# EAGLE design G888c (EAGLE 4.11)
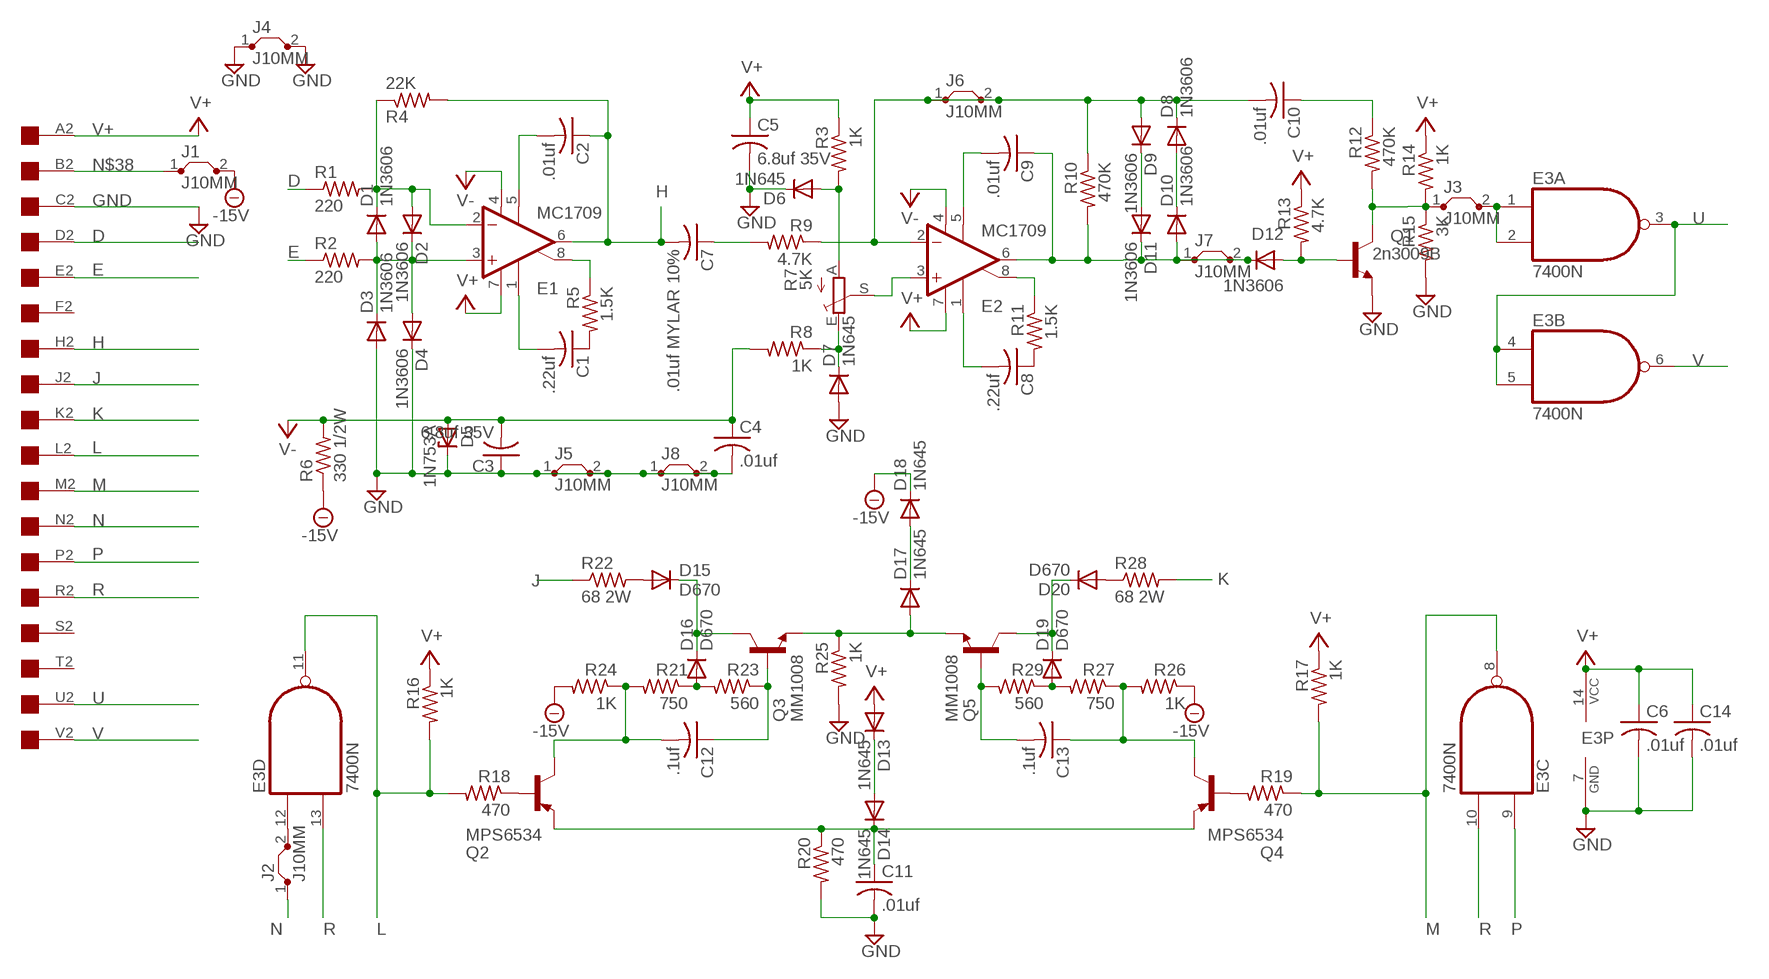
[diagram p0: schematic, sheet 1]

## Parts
C1  .22uf  C-US050-025X075  [C050-025X075]
C2  .01uf  C-US050-025X075  [C050-025X075]
C3  6.8uf 35V  C-US102-043X133  [C102-043X133]
C4  .01uf  C-US050-025X075  [C050-025X075]
C5  6.8uf 35V  C-US102-043X133  [C102-043X133]
C6  .01uf  C-US050-025X075  [C050-025X075]
C7  .01uf MYLAR 10%  C-US150-054X183  [C150-054X183]
C8  .22uf  C-US050-025X075  [C050-025X075]
C9  .01uf  C-US050-025X075  [C050-025X075]
C10  .01uf  C-US050-025X075  [C050-025X075]
C11  .01uf  C-US050-025X075  [C050-025X075]
C12  .1uf  C-US050-025X075  [C050-025X075]
C13  .1uf  C-US050-025X075  [C050-025X075]
C14  .01uf  C-US050-025X075  [C050-025X075]
D1  1N3606  1N4004  [DO41-10]
D2  1N3606  1N4004  [DO41-10]
D3  1N3606  1N4004  [DO41-10]
D4  1N3606  1N4004  [DO41-10]
D5  1N753A  ZENER-DIODEDO35Z10  [DO35Z10]
D6  1N645  1N4004  [DO41-10]
D7  1N645  1N4004  [DO41-10]
D8  1N3606  1N4004  [DO41-10]
D9  1N3606  1N4004  [DO41-10]
D10  1N3606  1N4004  [DO41-10]
D11  1N3606  1N4004  [DO41-10]
D12  1N3606  1N4004  [DO41-10]
D13  1N645  1N4004  [DO41-10]
D14  1N645  1N4004  [DO41-10]
D15  D670  1N4004  [DO41-10]
D16  D670  1N4004  [DO41-10]
D17  1N645  1N4004  [DO41-10]
D18  1N645  1N4004  [DO41-10]
D19  D670  1N4004  [DO41-10]
D20  D670  1N4004  [DO41-10]
E1  MC1709  LM3080N  [DIL08]
E2  MC1709  LM3080N  [DIL08]
E3  7400N  [DIL14]
J1  J10MM  [10]
J2  J10MM  [10]
J3  J10MM  [10]
J4  J10MM  [10]
J5  J10MM  [10]
J6  J10MM  [10]
J7  J10MM  [10]
J8  J10MM  [10]
Q1  2n3009B  2N1711  [TO39]
Q2  MPS6534  2N5415  [TO39]
Q3  MM1008  2N1711  [TO39]
Q4  MPS6534  2N5415  [TO39]
Q5  MM1008  2N1711  [TO39]
R1  220  R-US_0207/10  [0207/10]
R2  220  R-US_0207/10  [0207/10]
R3  1K  R-US_0207/10  [0207/10]
R4  22K  R-US_0207/10  [0207/10]
R5  1.5K  R-US_0207/10  [0207/10]
R6  330 1/2W  R-US_0411/15  [0411/15]
R7  5K  TRIM_EU-PTSPIN  [PT-SPIN]
R8  1K  R-US_0207/10  [0207/10]
R9  4.7K  R-US_0207/10  [0207/10]
R10  470K  R-US_0207/10  [0207/10]
R11  1.5K  R-US_0207/10  [0207/10]
R12  470K  R-US_0207/10  [0207/10]
R13  4.7K  R-US_0207/10  [0207/10]
R14  1K  R-US_0207/10  [0207/10]
R15  3K  R-US_0207/10  [0207/10]
R16  1K  R-US_0207/10  [0207/10]
R17  1K  R-US_0207/10  [0207/10]
R18  470  R-US_0207/10  [0207/10]
R19  470  R-US_0207/10  [0207/10]
R20  470  R-US_0207/10  [0207/10]
R21  750  R-US_0207/10  [0207/10]
R22  68 2W  R-US_0817/22  [P0817/22]
R23  560  R-US_0207/10  [0207/10]
R24  1K  R-US_0207/10  [0207/10]
R25  1K  R-US_0207/10  [0207/10]
R26  1K  R-US_0207/10  [0207/10]
R27  750  R-US_0207/10  [0207/10]
R28  68 2W  R-US_0817/22  [P0817/22]
R29  560  R-US_0207/10  [0207/10]
U$5  ONE-SIDED  [ONE-SIDED]

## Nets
-15V: D18.C J1.2 R6.1 R24.2 R26.1
D: R1.1 U$5.D2
E: R2.1 U$5.E2
GND: C3.1 C4.2 C5.2 C6.2 C11.2 C14.2 D3.A D4.C D5.C D6.C D7.A E3.7(P:GND) J4.1 J4.2 J5.1 J5.2 J8.1 J8.2 Q1.1(E) R15.2 R20.2 R25.2 U$5.C2
H: C2.1 C7.2 E1.6(OUT) R4.2 U$5.H2
J: R22.1 U$5.J2
K: R28.2 U$5.K2
L: E3.11(D:O) R16.2 R18.2 U$5.L2
M: E3.8(C:O) R17.2 R19.1 U$5.M2
N: J2.1 U$5.N2
N$1: C1.1 R5.2
N$2: C8.1 R11.2
N$3: D1.C D2.A E1.2(-IN) R1.2 R4.1
N$4: D1.A D2.C D3.C D4.A E1.3(+IN) R2.2
N$5: C8.2 E2.1(ON1)
N$6: C1.2 E1.1(ON1)
N$7: E1.8(ON2) R5.1
N$8: C2.2 E1.5(OPT)
N$9: D6.A R3.2 R7.A
N$10: C10.2 D8.C D9.A E2.2(-IN) J6.1 J6.2 R9.1 R10.1
N$11: E2.3(+IN) R7.S
N$12: D7.C R7.E R8.1
N$13: E2.8(ON2) R11.1
N$14: C9.2 E2.5(OPT)
N$15: C9.1 D10.A D11.C D12.C E2.6(OUT) J7.1 J7.2 R10.2
N$16: C7.1 R9.2
N$17: D9.C D11.A
N$18: D8.A D10.C
N$19: C10.1 R12.1
N$20: D12.A Q1.2(B) R13.2
N$21: J3.1 Q1.3(C) R12.2 R14.2 R15.1
N$22: D17.A Q3.1(E) Q5.1(E) R25.1
N$23: C11.1 D14.C Q2.1(E) Q4.1(E) R20.1
N$24: D13.C D14.A
N$25: Q2.2(B) R18.1
N$26: Q4.2(B) R19.2
N$27: D15.A R22.2
N$28: D16.A R21.1 R23.2
N$29: C12.2 Q2.3(C) R21.2 R24.1
N$30: C12.1 Q3.2(B) R23.1
N$31: D19.A R27.2 R29.1
N$32: C13.1 Q4.3(C) R26.2 R27.1
N$33: C13.2 Q5.2(B) R29.2
N$34: D20.A R28.1
N$35: D15.C D16.C Q3.3(C)
N$36: D19.C D20.C Q5.3(C)
N$37: D17.C D18.A
N$38: J1.1 U$5.B2
N$39: E3.12(D:I0) J2.2
N$40: E3.1(A:I0) E3.2(A:I1) J3.2
P: E3.9(C:I0) U$5.P2
R: E3.10(C:I1) E3.13(D:I1) U$5.R2
U: E3.3(A:O) E3.4(B:I0) E3.5(B:I1) U$5.U2
V: E3.6(B:O) U$5.V2
V+: C5.1 C6.1 C14.1 D13.A E1.7(V+) E2.7(V+) E3.14(P:VCC) R3.1 R13.1 R14.1 R16.1 R17.1 U$5.A2
V-: C3.2 C4.1 D5.A E1.4(V-) E2.4(V-) R6.2 R8.2
Unconnected: U$5.F2 U$5.S2 U$5.T2

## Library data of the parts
C1-C14 = rcl:C-US: CAPACITOR, American symbol
D1-D4 D6-D20 = diode:1N4004: DIODE
D5 = diode:ZENER-DIODE: Z-Diode
E1 E2 = linear:*3080: OP AMP
E3 = 74xx-us:74*00: Quad 2-input NAND gate
J1-J8 = jumper:J: Bridge
Q1 Q3 Q5 = transistor-npn:2N1711: NPN Transistor
Q2 Q4 = transistor-pnp:2N5415*: PNP Transistror
R1-R6 R8-R29 = rcl:R-US_: RESISTOR, American symbol
R7 = pot:TRIM_EU-: POTENTIOMETER
U$5 = con-dec:ONE-SIDED: One-sided DEC Flip-Chip single card fingers

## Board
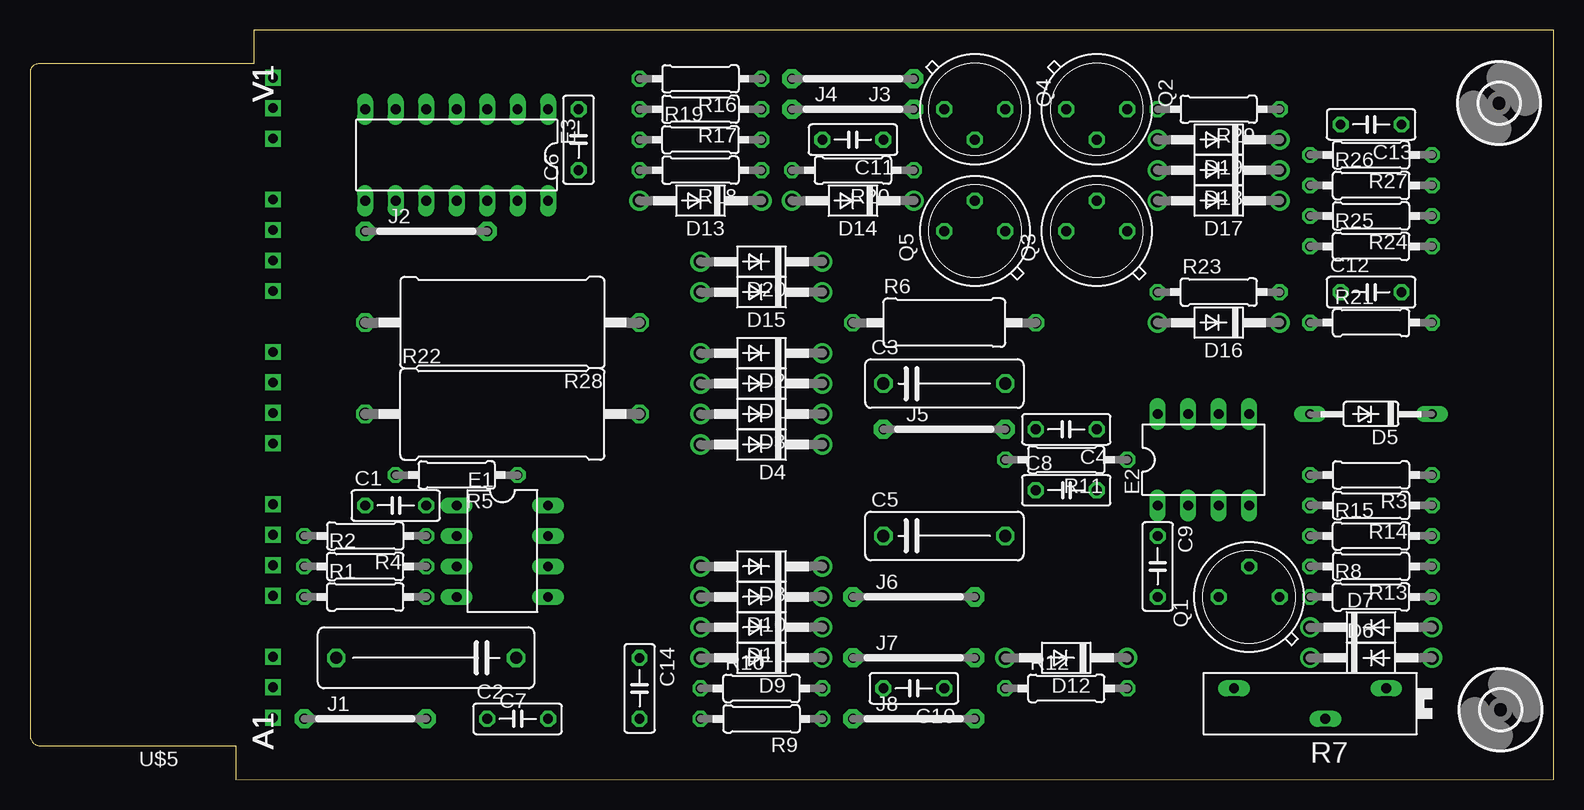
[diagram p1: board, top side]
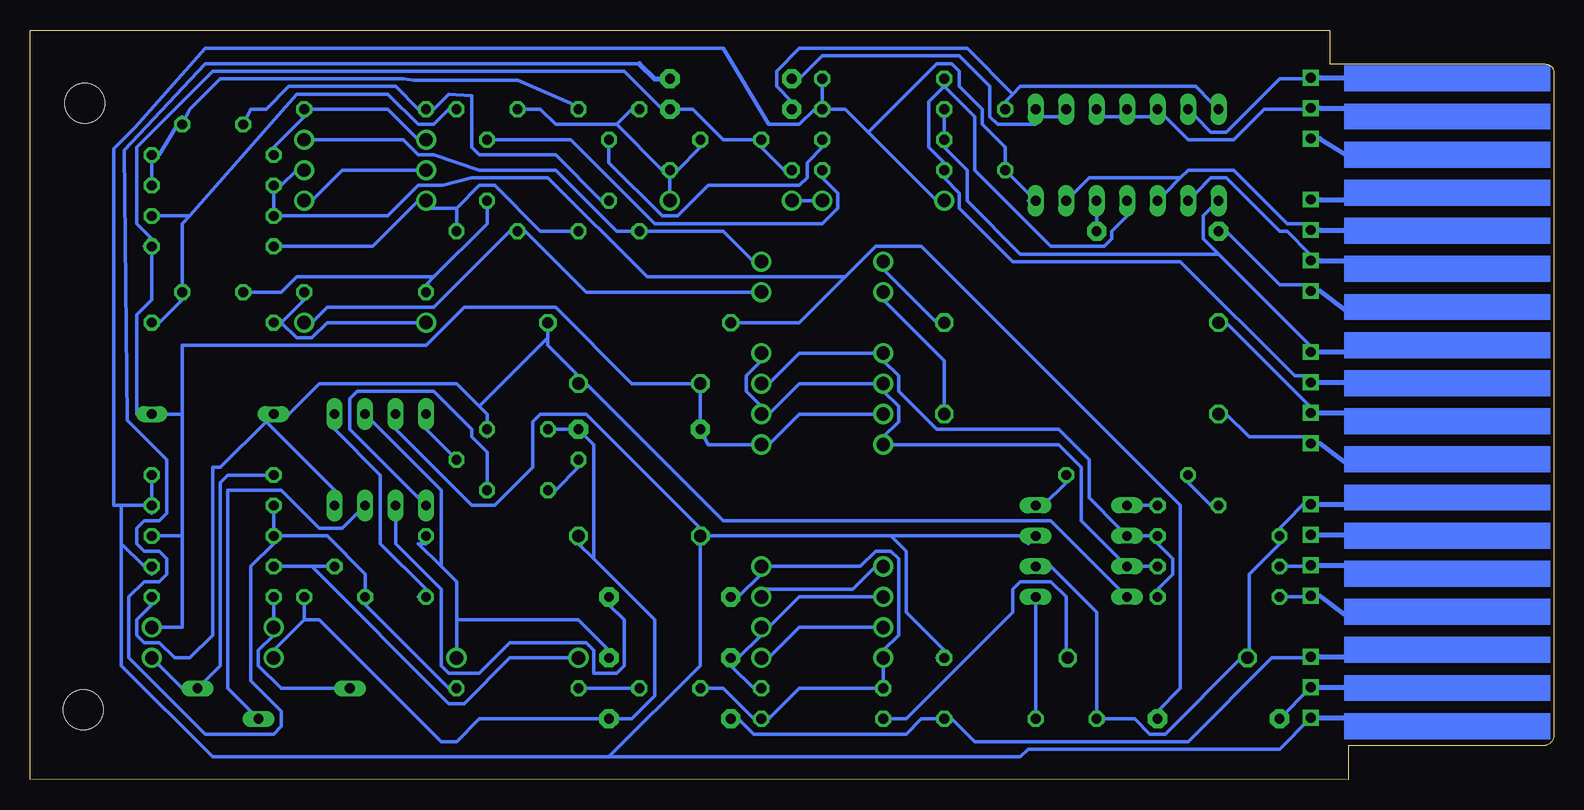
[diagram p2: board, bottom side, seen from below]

Size 126.98 x 62.48 mm. Coordinates in mm from the lower left corner, seen from the top.
Outline: 17.14,2.83 17.14,0 126.98,0.04 126.98,62.45 18.66,62.48 18.66,59.65 0.69,59.65 arc90 0,58.96 0,3.72 arc90 0.89,2.83 17.14,2.83
Copper layers (1*16): Top 0.035mm / dielectric 1.5mm / Bottom 0.035mm
Design rules "10mils": minimum track width 12mil, minimum drill 28mil, track to track 10mil, track to pad 10mil, pad to pad 10mil, via to via 10mil, smd to smd 10mil, copper to edge 40mil, drill to drill 10mil, minimum pad ring 10mil, minimum via ring 8mil, stop-mask expansion 0mil, vias tented up to drill 0mil, thermal gap 10mil

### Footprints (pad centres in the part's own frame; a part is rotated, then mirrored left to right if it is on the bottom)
C050-025X075 = drill 0.813 octagon: 1 -2.54,0; 2 2.54,0
C102-043X133 = drill 1.016 octagon: 1 -5.08,0; 2 5.08,0
C150-054X183 = drill 1.016 octagon: 1 -7.493,0; 2 7.493,0
DO41-10 = drill 1.118 round: A 5.08,0; C -5.08,0
DO35Z10 = drill 0.813 long: A 5.08,0; C -5.08,0
DIL08 = drill 0.813 long: 1 -3.81,-3.81; 2 -1.27,-3.81; 3 1.27,-3.81; 4 3.81,-3.81; 5 3.81,3.81; 6 1.27,3.81; 7 -1.27,3.81; 8 -3.81,3.81
DIL14 = drill 0.813 long: 1 -7.62,-3.81; 2 -5.08,-3.81; 3 -2.54,-3.81; 4 0,-3.81; 5 2.54,-3.81; 6 5.08,-3.81; 7 7.62,-3.81; 8 7.62,3.81; 9 5.08,3.81; 10 2.54,3.81; 11 0,3.81; 12 -2.54,3.81; 13 -5.08,3.81; 14 -7.62,3.81
10 = drill 0.813 pad 1.6 octagon: 1 -5.08,0; 2 5.08,0
TO39 = drill 0.813 octagon: 1 0,-2.54; 2 2.54,0; 3 0,2.54
0207/10 = drill 0.813 octagon: 1 -5.08,0; 2 5.08,0
0411/15 = drill 0.914 octagon: 1 -7.62,0; 2 7.62,0
PT-SPIN = drill 0.813 long: A -6.35,-1.27; E 6.35,-1.27; S -1.27,1.27
P0817/22 = drill 1.016 octagon: 1 -11.43,0; 2 11.43,0
3,3 = hole 3.3: 0,0
ONE-SIDED = drill 0.813 square: A2 20.256,5.175; B2 20.256,7.715; C2 20.256,10.255; D2 20.256,15.335; E2 20.256,17.875; F2 20.256,20.415; H2 20.256,22.955; J2 20.256,28.035; K2 20.256,30.575; L2 20.256,33.115; M2 20.256,35.655; N2 20.256,40.735; P2 20.256,43.275; R2 20.256,45.815; S2 20.256,48.355; T2 20.256,53.435; U2 20.256,55.975; V2 20.256,58.515

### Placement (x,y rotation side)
C1  30.48,22.86 0 top
C2  40.63,5.08 0 top
C3  76.2,33.02 0 top
C4  86.36,29.21 180 top
C5  76.2,20.32 0 top
C6  45.71,53.34 90 top
C7  33.02,10.16 180 top
C8  86.36,24.13 0 top
C9  93.98,17.78 270 top
C10  73.66,7.62 180 top
C11  68.58,53.34 180 top
C12  111.76,40.64 0 top
C13  111.76,54.61 180 top
C14  50.79,7.62 270 top
D1  60.95,33.02 180 top
D2  60.95,35.56 180 top
D3  60.95,30.48 180 top
D4  60.95,27.94 180 top
D5  111.76,30.48 180 top
D6  111.76,10.16 0 top
D7  111.76,12.7 0 top
D8  60.95,17.78 180 top
D9  60.95,10.16 180 top
D10  60.95,15.24 180 top
D11  60.95,12.7 180 top
D12  86.36,10.16 180 top
D13  55.88,48.26 180 top
D14  68.58,48.26 180 top
D15  60.95,40.64 180 top
D16  99.06,38.1 180 top
D17  99.06,48.26 180 top
D18  99.06,50.8 180 top
D19  99.06,53.34 180 top
D20  60.95,43.18 180 top
E1  39.36,19.05 270 top
E2  97.79,26.67 0 top
E3  35.55,52.07 180 top
J1  27.94,5.08 0 top
J2  33.02,45.72 0 top
J3  68.58,58.42 180 top
J4  68.58,55.88 0 top
J5  76.2,29.21 0 top
J6  73.66,15.24 0 top
J7  73.66,10.16 0 top
J8  73.66,5.08 0 top
Q1  101.59,15.24 90 top
Q2  88.9,55.88 270 top
Q3  88.9,45.72 90 top
Q4  78.73,55.88 270 top
Q5  78.73,45.72 90 top
R1  27.94,15.24 0 top
R2  27.94,17.78 0 top
R3  111.76,25.4 180 top
R4  27.94,20.32 180 top
R5  35.55,25.4 180 top
R6  76.2,38.1 0 top
R7  106.68,6.35 180 top
R8  111.76,15.24 0 top
R9  60.95,5.08 180 top
R10  60.95,7.62 0 top
R11  86.36,26.67 180 top
R12  86.36,7.62 0 top
R13  111.76,17.78 180 top
R14  111.76,22.86 180 top
R15  111.76,20.32 0 top
R16  55.88,58.42 180 top
R17  55.88,55.88 180 top
R18  55.88,50.8 180 top
R19  55.88,53.34 0 top
R20  68.58,50.8 180 top
R21  111.76,38.1 0 top
R22  39.36,30.48 0 top
R23  99.06,40.64 0 top
R24  111.76,46.99 180 top
R25  111.76,44.45 0 top
R26  111.76,49.53 0 top
R27  111.76,52.07 180 top
R28  39.36,38.1 180 top
R29  99.06,55.88 180 top
U$2  [3,3]  122.42,56.39 0 top
U$3  [3,3]  122.55,5.84 0 top
U$5  -0.01,0 0 top

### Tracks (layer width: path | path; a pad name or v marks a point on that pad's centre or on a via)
-15V
  Bottom 0.305: 59.05,41.91 56.51,44.45 52.7,44.45 31.11,22.86 31.11,7.62 33.02,5.71 J1.2 | 59.05,41.91 62.86,38.1 67.94,38.1 R6.1 | D18.C 104.77,50.8 106.04,49.53 R26.1 106.68,48.9 106.68,47.62 R24.2 106.04,46.99 104.77,46.99 97.15,46.99 94.61,49.53 92.58,49.53 90.17,50.16 83.81,50.16 75.56,41.91 59.05,41.91
D
  Bottom 0.305: U$5.D2 20.32,15.24 22.22,15.24 R1.1
E
  Bottom 0.305: U$5.E2 20.32,17.78 22.22,17.78 R2.1
GND
  Top 0.305: J4.1 64.13,55.88 67.94,55.88 73.02,55.88 J4.2 | J8.1 69.21,5.08
  Top 0.406: 69.21,5.08 J8.2 | J5.2 J5.1
  Bottom 0.305: 81.28,20.95 C5.2 81.28,19.68 80.01,18.41 | D3.A 56.51,30.48 62.86,30.48 65.4,27.94 D4.C 66.67,27.94 70.48,27.94 J5.1 71.12,28.57 71.12,32.38 C3.1 71.75,33.02 76.83,33.02 83.18,39.37 90.8,39.37 93.98,36.2 114.3,36.2 114.3,30.48 | J8.2 78.1,5.08 | U$5.C2 20.32,10.16 23.49,10.16 30.48,3.17 48.25,3.17 50.16,5.08 C14.2 51.43,5.08 52.7,5.08 53.97,3.81 66.67,3.81 67.94,5.08 J8.1 | 78.1,5.08 76.83,5.08 74.93,6.99 74.93,13.34 80.01,18.41 | J8.2 78.1,5.08 | J8.2 79.37,5.08 89.53,5.08 91.44,3.17 92.7,3.17 102.87,13.34 104.14,13.34 | 114.3,20.32 114.3,16.51 114.3,12.7 116.2,12.7 D7.A | 45.08,57.15 45.71,56.52 C6.2 | 45.08,57.15 44.45,57.78 29.84,57.78 28.57,56.52 E3.7 | 45.08,57.15 48.89,60.96 62.86,60.96 64.77,59.05 64.77,57.78 63.49,56.52 J4.1 | 104.14,13.34 104.14,14.61 Q1.1 | 104.14,13.34 106.68,10.79 D6.C | 114.3,20.32 116.2,20.32 R15.2 | 80.01,18.41 80.01,26.04 80.01,27.94 J5.2 81.91,29.21 83.18,29.21 C4.2 | R20.2 64.13,50.8 66.04,52.7 C11.2 66.67,53.34 69.21,53.34 71.75,55.88 73.02,55.88 J4.2 | 74.29,55.88 J4.2 | 114.3,30.48 114.3,20.32 | 114.3,30.48 115.56,30.48 D5.C 118.11,30.48 118.11,38.73 116.84,40.01 116.84,43.81 R25.2 | R25.2 117.47,44.45 | 74.29,55.88 77.47,59.05 111.76,59.05 118.11,52.7 118.11,46.35 116.84,45.09 R25.2 | 74.29,55.88 J4.2
H
  Bottom 0.305: U$5.H2 20.32,23.5 22.86,20.95 R4.2 22.86,19.68 25.39,17.14 25.39,10.79 C7.2 26.03,10.16 32.38,3.81 33.65,3.81 34.92,5.08 37.46,5.08 C2.1 38.09,5.71 38.09,13.97 41.9,17.78 E1.6
J
  Bottom 0.305: U$5.J2 20.32,28.57 25.39,28.57 27.3,30.48 R22.1
K
  Bottom 0.305: U$5.K2 20.32,31.11 27.3,38.1 R28.2
L
  Bottom 0.305: U$5.L2 20.32,33.66 21.59,33.66 31.11,43.18 45.08,43.18 49.52,47.62 49.52,48.9 50.79,50.16 R18.2 50.79,51.44 52.06,52.7 52.06,56.52 50.79,57.78 | 50.79,57.78 R16.2 50.79,57.78 | 50.79,57.78 48.25,55.24 48.25,50.8 41.9,44.45 37.46,44.45 36.82,45.09 36.82,45.72 35.55,46.99 E3.11
  Bottom 0.406: R16.2 50.79,57.91
M
  Bottom 0.305: 27.94,43.81 20.32,36.2 U$5.M2 | 27.94,43.81 28.57,44.45 29.21,45.09 29.21,46.99 28.57,47.62 E3.8 | R19.1 50.79,53.98 50.79,55.24 R17.2 | 50.79,52.7 R19.1 | 50.79,52.7 48.89,50.8 48.89,48.26 44.45,43.81 27.94,43.81 | 50.79,52.7 R19.1
N
  Bottom 0.305: U$5.N2 20.32,41.27 22.86,41.27 27.3,45.72 J2.1
N$1
  Bottom 0.305: C1.1 28.57,22.86 30.48,24.77 R5.2
N$2
  Bottom 0.305: C8.1 83.18,24.13 81.28,26.04 R11.2
N$3
  Bottom 0.305: R1.2 33.02,15.88 31.75,17.14 31.75,18.41 33.02,19.68 R4.1 33.65,20.32 34.28,20.32 E1.2 36.19,20.95 38.73,23.5 38.73,26.67 41.27,29.21 51.43,29.21 54.6,32.38 54.6,33.66 55.88,34.92 D2.A 56.51,35.56 62.86,35.56 65.4,33.02 D1.C
N$4
  Bottom 0.305: R2.2 33.65,17.78 34.28,17.78 E1.3 36.19,18.41 39.36,21.59 39.36,26.04 41.27,27.94 55.24,27.94 D4.A 55.88,28.57 54.6,29.84 54.6,31.11 55.88,32.38 D1.A 56.51,33.02 62.86,33.02 65.4,30.48 D3.C 66.04,31.11 67.31,32.38 67.31,33.66 66.04,34.92 D2.C
N$5
  Bottom 0.305: E2.1 94.61,23.5 100.33,29.21 100.33,31.75 99.69,32.38 93.34,32.38 90.17,29.21 90.17,28.57 88.9,27.3 88.9,24.77 C8.2
N$6
  Bottom 0.305: C1.2 33.65,22.86 34.28,22.86 E1.1
N$7
  Bottom 0.305: R5.1 40.63,24.77 42.54,22.86 E1.8
N$8
  Bottom 0.305: C2.2 43.17,5.71 43.17,14.61 E1.5
N$9
  Bottom 0.305: D6.A 114.3,7.62 R7.A 112.39,8.26 111.12,9.53 111.12,24.77 110.48,25.4 107.31,25.4 R3.2
N$10
  Top 0.406: J6.1 J6.2
  Bottom 0.305: C10.2 70.48,7.62 69.21,7.62 66.67,5.08 R9.1 65.4,5.08 62.86,7.62 56.51,7.62 R10.1 55.88,8.26 55.88,9.53 D9.A 55.88,10.79 54.6,12.06 54.6,18.41 55.24,19.05 56.51,19.05 57.78,17.78 65.4,17.78 D8.C 66.04,17.14 67.94,15.24 J6.1 68.58,15.88 | 79.37,15.24 J6.2 78.73,14.61 77.47,13.34 77.47,9.53 78.1,8.89 80.01,8.89 80.01,10.79 80.64,11.43 86.99,11.43 89.53,8.89 92.07,8.89 92.7,9.53 92.7,15.88 96.52,19.68 96.52,21.59 E2.2
N$11
  Bottom 0.305: 108.58,5.71 R7.S 108.58,5.71 | 108.58,5.71 110.48,7.62 110.48,24.13 106.04,24.13 102.87,20.95 100.96,20.95 99.69,22.23 E2.3
N$12
  Bottom 0.305: R7.E 101.59,7.62 106.04,7.62 107.95,9.53 107.95,10.79 106.68,12.06 D7.C 106.68,13.34 106.68,14.61 R8.1
N$13
  Bottom 0.305: R11.1 93.98,29.21 E2.8
N$14
  Bottom 0.305: 94.61,15.24 C9.2 93.98,15.88 97.79,19.68 97.79,25.4 101.59,29.21 E2.5
N$15
  Top 0.305: J7.1 69.21,10.16
  Top 0.406: 69.21,10.16 J7.2
  Bottom 0.305: 91.44,13.34 91.44,16.51 92.7,17.78 | 91.44,13.34 91.44,10.79 D12.C | 93.98,19.68 C9.1 93.98,19.68 | D10.A 56.51,15.24 62.86,15.24 65.4,12.7 D11.C 66.04,12.06 67.94,10.16 J7.1 68.58,9.53 66.67,7.62 R10.2 | 91.44,13.34 81.28,13.34 78.73,10.79 J7.2 | 92.7,17.78 94.61,19.68 93.98,19.68 | 92.7,17.78 92.7,24.13 98.42,29.84 E2.6
N$16
  Bottom 0.305: R9.2 55.24,5.08 53.97,5.08 45.08,13.97 45.08,15.88 44.45,16.51 41.9,16.51 40.63,15.24 40.63,10.79 C7.1
N$17
  Bottom 0.305: D11.A 56.51,12.7 62.86,12.7 65.4,10.16 D9.C
N$18
  Bottom 0.305: D8.A 56.51,17.78 58.41,15.88 66.04,15.88 D10.C
N$19
  Bottom 0.305: C10.1 76.83,7.62 80.64,7.62 R12.1
N$20
  Bottom 0.305: 103.5,17.78 102.23,17.78 Q1.2 | 103.5,17.78 106.04,17.78 R13.2 | 103.5,17.78 92.07,6.35 90.8,6.35 86.99,10.16 81.91,10.16 D12.A
N$21
  Top 0.406: J3.1 63.49,58.42
  Bottom 0.305: R12.2 92.07,7.62 99.06,14.61 Q1.3 99.06,17.14 102.23,20.32 R15.1 | R15.1 R14.2 | R15.1 106.68,19.68 108.58,17.78 108.58,8.26 106.04,5.71 106.04,4.45 106.68,3.81 112.39,3.81 118.74,10.16 118.74,15.24 117.47,16.51 116.2,16.51 115.56,17.14 115.56,18.41 116.2,19.05 117.47,19.05 118.11,19.68 118.11,20.95 117.47,21.59 116.2,21.59 115.56,22.23 115.56,26.67 118.87,29.97 119.12,52.45 112.39,59.69 76.2,59.69
  Bottom 0.406: J3.1 74.93,58.42 76.2,59.69
N$22
  Bottom 0.305: 91.44,47.62 89.53,49.53 88.26,49.53 84.45,45.72 81.91,45.72 Q5.1 | 91.44,47.62 91.44,46.35 Q3.1 | 91.44,47.62 93.98,47.62 D17.A 94.61,48.26 98.42,44.45 106.04,44.45 R25.1
N$23
  Bottom 0.305: 73.02,48.26 D14.C 73.66,48.9 73.66,50.16 R20.1 | 78.1,54.61 83.18,54.61 84.45,55.88 Q2.1 | 78.1,54.61 76.83,55.88 Q4.1 | C11.1 71.12,52.7 73.02,50.8 R20.1 | 78.1,54.61 74.29,50.8 R20.1
N$24
  Bottom 0.305: D13.C 61.59,48.26 62.86,48.26 D14.A
N$25
  Bottom 0.305: R18.1 60.95,50.16 59.68,48.9 59.68,47.62 60.95,46.35 74.93,46.35 81.91,53.34 88.26,53.34 Q2.2
N$26
  Bottom 0.305: R19.2 60.95,52.7 62.22,51.44 62.22,50.16 62.86,49.53 70.48,49.53 73.02,46.99 74.29,46.99 78.73,51.44 78.73,52.7 Q4.2
N$27
  Bottom 0.305: R22.2 50.79,31.11 50.79,34.92 55.88,40.01 D15.A
N$28
  Bottom 0.305: 104.14,40.01 R23.2 104.14,40.01 | D16.A 94.61,38.1 102.23,38.1 103.5,36.83 104.77,36.83 106.04,38.1 | 106.04,38.1 104.14,40.01 | 106.04,38.1 R21.1 106.04,38.1
N$29
  Bottom 0.305: 113.66,46.99 104.77,57.15 97.15,57.15 94.61,54.61 93.34,54.61 92.07,55.88 Q2.3 | 113.66,46.99 114.3,46.35 114.3,41.27 C12.2 114.3,40.01 116.2,38.1 R21.2 | 113.66,46.99 116.2,46.99 R24.1
N$30
  Bottom 0.305: 93.34,41.91 88.9,46.35 88.9,47.62 Q3.2 | 93.34,41.91 93.98,41.27 R23.1 | 93.34,41.91 104.77,41.91 106.04,40.64 108.58,40.64 C12.1
N$31
  Bottom 0.305: 93.98,53.98 D19.A 94.61,53.34 97.15,55.88 103.5,55.88 | 103.5,55.88 R29.1 | 103.5,55.88 R29.1 | R27.2 106.68,52.7 104.14,55.24 R29.1
N$32
  Bottom 0.305: Q4.3 81.91,56.39 86.36,58.29 94.99,58.29 95.88,58.42 111.12,58.42 111.76,57.78 113.66,55.88 C13.1 114.3,55.24 116.2,52.07 R27.1 116.84,51.44 116.84,50.16 R26.2
N$33
  Bottom 0.305: Q5.2 79.37,48.26 83.18,52.07 89.53,52.07 90.17,52.7 90.17,57.02 92.07,57.15 93.34,55.88 R29.2 94.61,55.88 96.52,57.78 105.41,57.78 107.31,55.88 108.58,55.88 C13.2
N$34
  Bottom 0.305: R28.1 51.43,38.1 55.88,42.55 D20.A
N$35
  Bottom 0.305: D15.C 66.67,40.64 80.64,40.64 85.72,45.72 Q3.3 86.99,45.72 93.34,39.37 102.23,39.37 103.5,38.1 D16.C
N$36
  Bottom 0.305: D20.C 66.67,43.18 69.21,45.72 75.56,45.72 Q5.3 76.83,45.72 78.1,45.72 83.18,50.8 88.26,50.8 89.53,50.8 93.34,52.07 94.61,52.07 95.88,53.34 103.5,53.34 D19.C
N$37
  Bottom 0.305: D18.A 94.61,50.8 100.96,50.8 103.5,48.26 D17.C
N$38
  Bottom 0.305: J1.1 20.32,7.62 U$5.B2
N$39
  Bottom 0.305: E3.12 38.09,46.99 38.09,46.35 J2.2
N$40
  Bottom 0.305: E3.2 41.27,55.24 42.54,55.24 E3.1 43.17,54.61 46.35,54.61 46.98,55.24 46.98,56.52 46.98,57.78 49.52,60.33 60.95,60.33 62.86,58.42 | 62.86,58.42 J3.2 62.86,58.42
P
  Bottom 0.305: U$5.P2 20.32,43.81 22.22,45.72 22.86,45.72 27.3,50.16 28.57,50.16 29.84,48.9 E3.9
R
  Bottom 0.305: 31.11,50.16 32.38,48.9 E3.10 | 31.11,50.16 30.48,50.8 26.67,50.8 22.22,46.35 20.32,46.35 U$5.R2 | 31.11,50.16 38.73,50.16 40,48.9 E3.13
U
  Bottom 0.305: E3.3 37.46,55.24 36.19,55.24 E3.4 34.92,55.24 33.65,55.24 E3.5 32.38,55.24 30.48,53.34 26.67,53.34 24.12,55.88 20.32,55.88 U$5.U2
V
  Bottom 0.305: U$5.V2 20.32,58.42 22.86,58.42 27.3,53.98 28.57,53.98 29.84,55.24 E3.6
V+
  Bottom 0.305: R17.1 R16.1 | 50.16,48.26 D13.A 51.43,48.26 57.14,53.98 | 43.81,48.26 E3.14 C6.1 45.71,52.7 47.62,54.61 47.62,55.88 49.52,57.78 49.52,59.05 50.16,59.69 51.43,59.69 57.14,53.98 | 57.14,53.98 59.05,55.88 R17.1 | 51.43,10.16 C14.1 50.79,10.79 53.97,13.97 53.97,19.05 55.24,20.32 | 43.81,19.68 E1.7 55.24,20.32 | 116.84,17.14 R13.1 117.47,17.78 119.38,19.68 | C5.1 55.24,20.32 | U$5.A2 20.32,5.08 22.86,2.54 43.81,2.54 44.45,1.91 78.73,1.91 | R17.1 61.59,55.88 62.86,54.61 65.4,54.61 69.21,60.96 112.39,60.96 118.23,54.36 120.01,52.58 120.01,22.86 119.38,22.86 | 119.38,22.86 R14.1 | R14.1 116.84,22.23 | R14.1 R3.1 | 119.38,19.68 119.38,22.86 | 119.38,10.16 119.38,19.68 | 119.38,10.16 119.38,10.03 | 78.73,1.91 111.76,1.91 119.38,9.53 119.38,10.16 | 78.73,1.91 71.12,9.53 C5.1 | E2.7 96.52,29.21 90.17,22.86 88.26,22.86 85.09,26.04 85.09,29.84 84.45,30.48 80.64,30.48 71.12,20.95 C5.1
V-
  Bottom 0.305: E1.4 36.19,15.88 41.9,21.59 69.21,21.59 80.64,33.02 C3.2 81.28,33.66 81.91,34.29 83.81,36.2 83.81,36.83 | R8.2 116.84,14.61 118.11,13.34 118.11,12.06 117.47,11.43 116.2,11.43 114.93,10.16 113.66,10.16 111.76,12.06 111.76,26.04 111.12,26.04 107.31,29.84 | 107.31,29.84 101.59,24.13 E2.4 | D5.A 107.31,29.84 | D5.A 107.31,29.84 | D5.A 105.41,30.48 102.87,33.02 91.44,33.02 89.53,31.11 | C4.1 88.9,28.57 C4.1 | C4.1 88.9,30.48 89.53,31.11 | 83.81,36.83 83.81,37.47 R6.2 | 83.81,36.83 89.53,31.11

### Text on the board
tNames: V1 | V1 | V1 | V1 | V1 | V1 | V1 | V1 | V1 | V1 | V1 | V1 | V1 | V1 | V1 | V1 | V1 | V1 | V1 | V1 | V1 | V1 | V1 | V1 | V1 | V1 | V1 | V1 | V1 | V1 | V1 | V1 | A1 | A1 | A1 | A1 | A1 | A1 | A1 | A1 | A1 | A1 | A1 | A1 | A1 | A1 | A1 | A1 | A1 | A1 | A1 | A1 | A1 | A1 | A1 | A1 | A1 | A1 | A1 | A1 | A1 | A1 | A1 | A1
